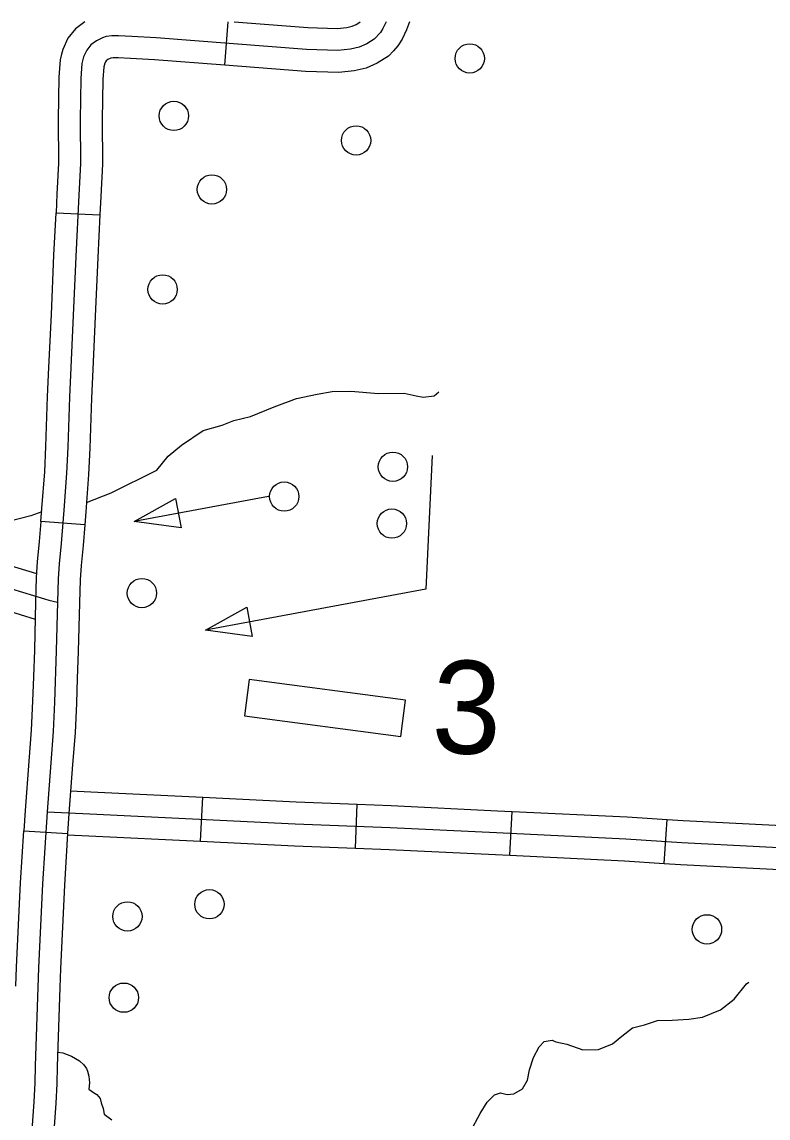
# Model space of a CAD drawing. Extents: x 653372 to 905732, y 627442 to 787275.
# Drawn here: x 693379 to 695924, y 783537 to 787275 of the extents above; entities that cross this region are included whole.
import ezdxf

# ---------------------------------------------------------------- set-up
doc = ezdxf.new("R2010")
doc.units = 0
for name, color, linetype in [('31', 7, 'Continuous'), ('32', 7, 'Continuous'), ('35', 7, 'Continuous'), ('56', 7, 'Continuous'), ('57', 7, 'Continuous')]:
    doc.layers.add(name, color=color, linetype=linetype)

msp = doc.modelspace()

# ---------------------------------------------------------------- linework, layer by layer
at = {"layer": '31'}
for p, q in [((694071.5, 787126.7), (694082.9, 787274.7)), ((693495.6, 786623.8), (693645.4, 786616.6)), ((693593.6, 785559.6), (693444.1, 785571.5)), ((693385.6, 784516.3), (693535.3, 784506.7)), ((693535.3, 784506.7), (693535.3, 784506.7))]:
    msp.add_line(p, q, dxfattribs=at)
for points in [[(693594.1, 787274.7), (693562.2, 787250.9), (693536.2, 787218.8), (693518.5, 787180.7), (693514.7, 787164.9)], [(694620.9, 787274.7), (694610.5, 787252.2), (694602.1, 787239.2), (694580.5, 787216.1), (694555.4, 787199.8), (694529.5, 787188.3), (694500, 787181.6), (694457.2, 787177.2), (694350.3, 787180.4), (693837.3, 787220)], [(694102.8, 787274.7), (694354.3, 787255.3), (694454.5, 787252.3), (694487.8, 787255.8), (694505.8, 787259.8), (694519.5, 787266), (694532, 787274), (694532.7, 787274.7)], [(694701.4, 787274.7), (694690.8, 787247.3), (694676.4, 787215.9), (694661.4, 787192.8), (694646, 787176.3)], [(693837.3, 787220), (693753.7, 787225.3), (693709.2, 787227.1), (693686.5, 787226.9), (693666.1, 787224.6), (693654.6, 787220.7), (693633.4, 787210.5), (693614.5, 787196.4), (693600.3, 787178.8), (693589.7, 787155.9), (693584.2, 787133.3), (693579.9, 787082.3), (693578.5, 786941.2), (693578.7, 786791.5), (693573.6, 786683.4), (693563.5, 786475.3), (693554.6, 786273.8), (693541.5, 785994.8), (693535.5, 785824.5), (693531.9, 785735.6), (693522.4, 785609.8), (693513.3, 785496.1), (693506.5, 785427.1), (693503.1, 785376.1), (693500.7, 785295.6), (693496.6, 785130), (693490.4, 784954.9), (693485.5, 784854.7), (693477.6, 784747.9), (693464.9, 784580.6), (693449.1, 784335.2), (693435.7, 784048.6), (693424.8, 783715.4), (693423, 783656.7), (693420.2, 783592.4), (693412, 783479.9)], [(693514.7, 787164.9), (693510, 787145.3), (693504.9, 787085.9), (693503.5, 786941.5), (693503.7, 786793.3), (693498.7, 786687), (693495.6, 786623.8)], [(694646, 787176.3), (694629.1, 787158.2), (694591.3, 787133.7), (694553.3, 787116.8), (694512.1, 787107.5), (694459.9, 787102.1), (694346.3, 787105.5), (694071.5, 787126.7)], [(693660.6, 787129.9), (693658.5, 787121.3), (693654.8, 787078.7), (693653.5, 786940.9), (693653.7, 786789.8), (693648.5, 786679.8), (693645.4, 786616.6)], [(694071.5, 787126.7), (693832, 787145.2), (693749.7, 787150.4), (693708.1, 787152.1), (693691, 787151.9), (693682.7, 787151), (693672.6, 787146.1), (693666.9, 787141.9), (693664.4, 787138.8), (693660.8, 787131.1), (693660.6, 787129.9)], [(693471.2, 786096.3), (693479.7, 786277.2), (693488.6, 786478.8), (693495.6, 786623.8)], [(693645.4, 786616.6), (693638.5, 786471.9), (693629.6, 786270.4), (693621.1, 786089.3)], [(693444.1, 785571.5), (693447.6, 785615.7), (693457, 785739.9), (693460.5, 785827.3), (693466.6, 785997.9), (693471.2, 786096.3)], [(693621.1, 786089.3), (693616.5, 785991.7), (693610.4, 785821.6), (693606.7, 785731.2), (693597.2, 785604), (693593.6, 785559.6)], [(693444.1, 785571.5), (693438.6, 785502.7), (693431.7, 785433.3), (693428.1, 785379.7), (693425.7, 785297.7), (693421.7, 785132.2), (693418.4, 785041)], [(693593.6, 785559.6), (693588, 785489.4), (693581.2, 785420.9), (693578, 785372.4), (693575.6, 785293.6), (693571.6, 785127.7), (693568.3, 785035.7)], [(693418.4, 785041), (693415.5, 784958.1), (693410.7, 784859.3), (693402.8, 784753.5), (693390, 784585.9), (693385.6, 784516.3)], [(693568.3, 785035.7), (693565.4, 784951.8), (693560.4, 784850.1), (693552.4, 784742.2), (693539.7, 784575.4), (693535.3, 784506.7)], [(693358.7, 783986.7), (693360.8, 784051.6), (693374.2, 784339.4), (693385.6, 784516.3)], [(693535.3, 784506.7), (693524, 784331.1), (693510.7, 784045.6), (693508.6, 783981.7)], [(693508.6, 783981.7), (693499.8, 783713.1), (693498, 783653.9), (693495, 783588), (693486.9, 783475), (693485.5, 783452.3)]]:
    msp.add_lwpolyline(points, dxfattribs=at)
at = {"layer": '32'}
for p, q in [((693988.6, 784480.8), (693995.9, 784630.6)), ((694516.7, 784457), (694522.7, 784606.9)), ((695043.6, 784432.8), (695050.7, 784582.6)), ((695569.2, 784405.1), (695579.6, 784554.7))]:
    msp.add_line(p, q, dxfattribs=at)
for points in [[(692997.3, 785554.2), (693005.8, 785549.2), (693037.5, 785532.9), (693087.6, 785507.4), (693109, 785497.2), (693159.7, 785477.6), (693207, 785460.7), (693259.4, 785445), (693300.5, 785432.7), (693365.4, 785413.4), (693429.1, 785393.8)], [(692921.4, 785424.8), (692933.5, 785417.8), (692969.1, 785399.4), (693021.3, 785372.8), (693049.6, 785359.3), (693107.5, 785337), (693160.2, 785318.2), (693216.3, 785301.3), (693257.6, 785288.9), (693322, 785269.8), (693424.2, 785238.4)], [(693343.7, 785341.6), (693456.2, 785307), (693471.7, 785302.8), (693500.7, 785295.6)], [(693545.5, 784652.1), (693614.5, 784649), (693995.9, 784630.6)], [(693995.9, 784630.6), (694314.9, 784615.2), (694522.7, 784606.9)], [(694522.7, 784606.9), (694638.2, 784602.2), (695001, 784584.9), (695050.7, 784582.6)], [(695050.7, 784582.6), (695443.3, 784564.2), (695579.6, 784554.7)], [(693464.9, 784580.6), (693611, 784574.1), (694311.6, 784540.2), (694634.9, 784527.3), (694997.5, 784510), (695439, 784489.3), (695630.1, 784476.1), (696159, 784449.5), (696436.3, 784436.9), (696504, 784432.7), (696542.3, 784428.4), (696579.4, 784420.9), (696602.7, 784413.7), (696611.2, 784412.4), (696651.6, 784406.9), (696717.7, 784400.7), (696832.8, 784394), (696944.8, 784388.5), (697097.3, 784382.9), (697420, 784362.9)], [(695579.6, 784554.7), (695634.5, 784550.9), (696105.4, 784527.3)], [(693535, 784502.4), (693607.5, 784499.2), (693988.6, 784480.8)], [(693988.6, 784480.8), (694308.3, 784465.3), (694516.7, 784457)], [(694516.7, 784457), (694631.6, 784452.4), (694993.9, 784435.1), (695043.6, 784432.8)], [(695043.6, 784432.8), (695434.6, 784414.4), (695569.2, 784405.1)], [(695569.2, 784405.1), (695625.6, 784401.2), (696097.9, 784377.5)]]:
    msp.add_lwpolyline(points, dxfattribs=at)
at = {"layer": '35'}
for points in [[(693599.6, 785636.1), (693683.6, 785668.5), (693839.8, 785745.6), (693877.9, 785794.2), (693924, 785831.9), (693997.8, 785881.8), (694062, 785899.3), (694101.8, 785915.4), (694159.1, 785929.1), (694239.4, 785962.3), (694316.1, 785990.8), (694386.4, 786005.2), (694437.6, 786014.4), (694501, 786016), (694595.5, 786007.2), (694683.2, 786008.2), (694723.2, 785999.9), (694748, 785995.6), (694784.8, 785999.2), (694800.6, 786013.2)], [(693446.8, 785604.1), (693409.7, 785590.3), (693334.5, 785571.3), (693299.6, 785553.5), (693225.9, 785547.4), (693190.5, 785549.5), (693173.1, 785563), (693142, 785593.6), (693115.6, 785621.6), (693109.4, 785633.9)], [(694909.3, 783491), (694942.4, 783552.4), (694965.3, 783591.3), (694990.7, 783616.2), (695011.7, 783623.1), (695034.3, 783616.7), (695057.1, 783619.9), (695086.9, 783636), (695103, 783665.8), (695109.7, 783700.7), (695124.3, 783743.8), (695143.3, 783779.2), (695160, 783797.6), (695180.9, 783800.8), (695187.6, 783802.5), (695199.7, 783796.4), (695237.7, 783788.4), (695292.1, 783769.7), (695345.1, 783770), (695393.1, 783789.4), (695425.1, 783815.9), (695461.9, 783844.2), (695502, 783854.4), (695547, 783869.1), (695596.2, 783870.5), (695654.1, 783874.4), (695700.7, 783880.6), (695762.1, 783906.2), (695807.7, 783942.7), (695850, 783994.5), (695857.7, 784000.4)], [(693501.3, 783761.3), (693518.7, 783759.6), (693548.7, 783747.3), (693575.7, 783732.3), (693590.4, 783717.7), (693599.5, 783706), (693603, 783696.5), (693607.2, 783679.3), (693609.4, 783656.5), (693607.8, 783634.7), (693623.5, 783623.9), (693634.7, 783616.9), (693646.6, 783603.3), (693650, 783589), (693656, 783568.9), (693660.1, 783549.8), (693686.1, 783531)]]:
    msp.add_lwpolyline(points, dxfattribs=at)
at = {"layer": '56'}
for p, q in [((693762.2, 785571.6), (693903.5, 785649.5)), ((693903.5, 785649.5), (693921.9, 785549.2)), ((693921.9, 785549.2), (693762.2, 785571.6)), ((694004.9, 785200.6), (694146, 785278.8)), ((694146, 785278.8), (694164.7, 785178.5)), ((694164.7, 785178.5), (694004.9, 785200.6))]:
    msp.add_line(p, q, dxfattribs=at)
for points in [[(694778, 785796.4), (694756.7, 785340.7), (694004.9, 785200.6)], [(694220.5, 785656), (693762.2, 785571.6)]]:
    msp.add_lwpolyline(points, dxfattribs=at)
for centre in [(694906.4, 787150.4), (693897.4, 786954.1), (694519, 786870.5), (694027.3, 786703.6), (693859.2, 786362.6), (694644.5, 785757.8), (694273.8, 785656), (694640.9, 785563.9), (693788.4, 785327), (694018.9, 784265.7), (693739, 784224.2), (695715.4, 784180.3), (693726.9, 783947.3)]:
    msp.add_circle(centre, 50, dxfattribs=at)
at = {"layer": '57'}
for p, q in [((694154.3, 785031.9), (694138, 784908)), ((694687.2, 784962), (694154.3, 785031.9)), ((694670.9, 784838.1), (694687.2, 784962)), ((694138, 784908), (694670.9, 784838.1))]:
    msp.add_line(p, q, dxfattribs=at)

# ---------------------------------------------------------------- texts
msp.add_text('3', height=316.8, rotation=358.28, dxfattribs=at).set_placement((694773.9, 784782.9))

doc.saveas('drawing.dxf')
